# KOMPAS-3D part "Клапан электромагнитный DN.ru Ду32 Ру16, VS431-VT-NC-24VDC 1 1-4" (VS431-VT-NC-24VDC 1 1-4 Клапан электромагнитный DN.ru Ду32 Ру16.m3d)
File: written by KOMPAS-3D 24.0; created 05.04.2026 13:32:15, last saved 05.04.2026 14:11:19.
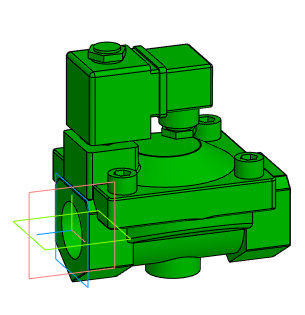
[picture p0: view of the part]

Document properties: Автор: artio; Полное имя файла: C:\Users\artio\OneDrive\Рабочий стол\Клапан электромагнитный DN.ru\VS431\VS431-VT-NC\VS431-VT-NC-24VDC\Ду32\VS431-VT-NC-24VDC 1 1-4 Клапан электромагнитный DN.ru Ду32 Ру16.m3d

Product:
- Body: Тело 1  | qty 1
    Масса: 3.709873
- Part/product: Клапан электромагнитный DN.ru Ду32 Ру16  | designation VS431-VT-NC-24VDC 1 1-4
    Масса: 1.701
    Раздел спецификации: Прочие изделия
    Примечание: D130-04757
    additional columns: ef56311e-7521-43dc-8291-0e6108b3d81d; artio; c; Шероховатость не задана; Да

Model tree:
1. Операция без истории:1

Expressions: VS431-VT-NC-24VDC 1 1-4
